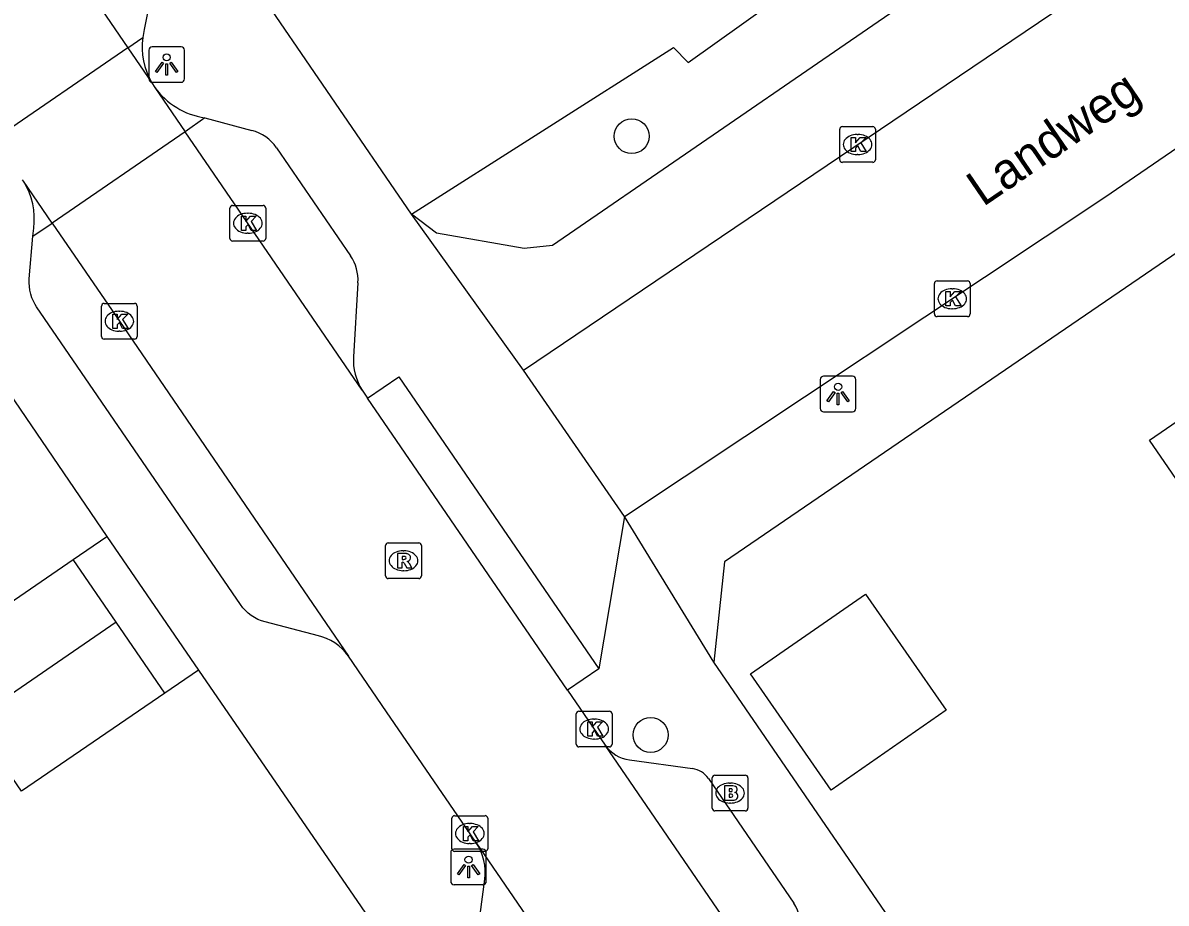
# Model space of a CAD drawing. Extents: x 157466 to 158888, y 383063 to 384677.
# Drawn here: x 158452.4 to 158484.41, y 383630.52 to 383655.18 of the extents above; entities that cross this region are included whole.
import ezdxf

# ---------------------------------------------------------------- set-up
doc = ezdxf.new("R2010")
doc.units = 0
for name, color, linetype in [('IMGEO_Boom', 7, 'Continuous'), ('IMGEO_Brandkraan', 7, 'Continuous'), ('IMGEO_Groenvoorziening', 7, 'Continuous'), ('IMGEO_Kolk', 7, 'Continuous'), ('IMGEO_Lichtpunt', 7, 'Continuous'), ('IMGEO_Openbare_ruimte_label', 7, 'Continuous'), ('IMGEO_Pand', 7, 'Continuous'), ('IMGEO_Parkeervlak_open', 7, 'Continuous'), ('IMGEO_Rijbaan_lokaal_open', 7, 'Continuous'), ('IMGEO_Rioolput', 7, 'Continuous'), ('IMGEO_Voetpad_open', 7, 'Continuous')]:
    doc.layers.add(name, color=color, linetype=linetype)

msp = doc.modelspace()

# ---------------------------------------------------------------- linework, layer by layer
at = {"layer": 'IMGEO_Boom'}
for centre in [(158469.446, 383652.007), (158469.975, 383635.235)]:
    msp.add_circle(centre, 0.489, dxfattribs=at)
at = {"layer": 'IMGEO_Brandkraan'}
for p, q in [((158471.7, 383633.182), (158471.7, 383634.034)), ((158471.775, 383634.108), (158472.627, 383634.108)), ((158472.701, 383634.034), (158472.701, 383633.182)), ((158472.188, 383633.888), (158472.213, 383633.888)), ((158472.627, 383633.108), (158471.775, 383633.108)), ((158472.211, 383633.328), (158472.186, 383633.328))]:
    msp.add_line(p, q, dxfattribs=at)
for points in [[(158471.7, 383633.182), (158471.7, 383634.034)], [(158471.775, 383634.108), (158472.627, 383634.108)], [(158472.701, 383634.034), (158472.701, 383633.182)], [(158472.048, 383633.808), (158472.048, 383633.408), (158472.261, 383633.408)], [(158472.279, 383633.808), (158472.048, 383633.808)], [(158472.227, 383633.727), (158472.173, 383633.727), (158472.173, 383633.651)], [(158472.173, 383633.651), (158472.226, 383633.651)], [(158472.235, 383633.575), (158472.173, 383633.575), (158472.173, 383633.494)], [(158472.173, 383633.494), (158472.235, 383633.494)], [(158472.627, 383633.108), (158471.775, 383633.108)]]:
    msp.add_lwpolyline(points, dxfattribs=at)
for centre, radius, start, end in [((158471.777, 383634.032), 0.0765, 91.552, 178.448), ((158471.777, 383634.032), 0.0765, 91.552, 178.448), ((158472.625, 383634.032), 0.0765, 1.552, 88.448), ((158472.625, 383634.032), 0.0765, 1.552, 88.448), ((158472.228, 383633.689), 0.0379, 267.8285, 90.9355), ((158472.283, 383633.663), 0.145, 59.4692, 91.5367), ((158472.308, 383633.71), 0.0922, 285.5137, 58.1501), ((158472.236, 383633.534), 0.0404, 269.8759, 90.5077), ((158472.267, 383633.659), 0.251, 268.6676, 293.5347), ((158472.313, 383633.518), 0.105, 301.3115, 78.989), ((158471.777, 383633.184), 0.0765, 181.552, 268.448), ((158471.777, 383633.184), 0.0765, 181.552, 268.448), ((158472.625, 383633.184), 0.0765, 271.552, 358.448), ((158472.625, 383633.184), 0.0765, 271.552, 358.448)]:
    msp.add_arc(centre, radius, start, end, dxfattribs=at)
for centre, major_axis, ratio, start_param, end_param in [((158472.187, 383633.608), (-0.387, 0.002), 0.722429, 4.712389, 7.853982), ((158472.212, 383633.608), (-0.39, 0.002), 0.717154, 1.570796, 4.712389)]:
    msp.add_ellipse(centre, major_axis=major_axis, ratio=ratio, start_param=start_param, end_param=end_param, dxfattribs=at)
at = {"layer": 'IMGEO_Groenvoorziening'}
msp.add_lwpolyline([(158463.285, 383649.821), (158470.621, 383654.492), (158471.026, 383654.075), (158477.748, 383658.874), (158478.003, 383659.037)], dxfattribs=at)
at = {"layer": 'IMGEO_Kolk'}
for p, q in [((158475.345, 383652.275), (158476.197, 383652.275)), ((158475.27, 383651.349), (158475.27, 383652.201)), ((158475.758, 383652.055), (158475.783, 383652.055)), ((158476.271, 383652.201), (158476.271, 383651.349)), ((158475.781, 383651.495), (158475.756, 383651.495)), ((158476.197, 383651.275), (158475.345, 383651.275)), ((158458.273, 383650.069), (158459.125, 383650.069)), ((158458.198, 383649.143), (158458.198, 383649.995)), ((158458.686, 383649.849), (158458.711, 383649.849)), ((158459.199, 383649.995), (158459.199, 383649.143)), ((158459.125, 383649.069), (158458.273, 383649.069)), ((158458.709, 383649.289), (158458.684, 383649.289)), ((158477.922, 383647.028), (158477.922, 383647.88)), ((158477.997, 383647.954), (158478.849, 383647.954)), ((158478.923, 383647.88), (158478.923, 383647.028)), ((158478.41, 383647.734), (158478.435, 383647.734)), ((158454.6, 383646.397), (158454.6, 383647.249)), ((158454.675, 383647.323), (158455.527, 383647.323)), ((158455.601, 383647.249), (158455.601, 383646.397)), ((158478.433, 383647.174), (158478.408, 383647.174)), ((158455.088, 383647.103), (158455.113, 383647.103)), ((158478.849, 383646.954), (158477.997, 383646.954)), ((158455.111, 383646.543), (158455.086, 383646.543)), ((158455.527, 383646.323), (158454.675, 383646.323)), ((158467.895, 383634.975), (158467.895, 383635.827)), ((158467.97, 383635.901), (158468.822, 383635.901)), ((158468.383, 383635.681), (158468.408, 383635.681)), ((158468.896, 383635.827), (158468.896, 383634.975)), ((158468.406, 383635.121), (158468.381, 383635.121)), ((158468.822, 383634.901), (158467.97, 383634.901)), ((158464.414, 383632.048), (158464.414, 383632.9)), ((158464.489, 383632.974), (158465.341, 383632.974)), ((158464.902, 383632.754), (158464.927, 383632.754)), ((158465.415, 383632.9), (158465.415, 383632.048)), ((158464.925, 383632.194), (158464.9, 383632.194)), ((158465.341, 383631.974), (158464.489, 383631.974))]:
    msp.add_line(p, q, dxfattribs=at)
for points in [[(158475.345, 383652.275), (158476.197, 383652.275)], [(158475.27, 383651.349), (158475.27, 383652.201)], [(158475.591, 383651.975), (158475.714, 383651.975), (158475.714, 383651.824), (158475.844, 383651.975), (158476.008, 383651.975), (158475.862, 383651.824), (158476.015, 383651.575), (158475.863, 383651.575), (158475.778, 383651.739), (158475.714, 383651.672), (158475.714, 383651.575), (158475.591, 383651.575), (158475.591, 383651.975)], [(158476.271, 383652.201), (158476.271, 383651.349)], [(158476.197, 383651.275), (158475.345, 383651.275)], [(158458.273, 383650.069), (158459.125, 383650.069)], [(158458.198, 383649.143), (158458.198, 383649.995)], [(158458.519, 383649.769), (158458.642, 383649.769), (158458.642, 383649.618), (158458.772, 383649.769), (158458.936, 383649.769), (158458.79, 383649.618), (158458.943, 383649.369), (158458.791, 383649.369), (158458.706, 383649.533), (158458.642, 383649.466), (158458.642, 383649.369), (158458.519, 383649.369), (158458.519, 383649.769)], [(158459.199, 383649.995), (158459.199, 383649.143)], [(158459.125, 383649.069), (158458.273, 383649.069)], [(158477.922, 383647.028), (158477.922, 383647.88)], [(158477.997, 383647.954), (158478.849, 383647.954)], [(158478.923, 383647.88), (158478.923, 383647.028)], [(158478.243, 383647.654), (158478.366, 383647.654), (158478.366, 383647.503), (158478.496, 383647.654), (158478.66, 383647.654), (158478.514, 383647.503), (158478.667, 383647.254), (158478.515, 383647.254), (158478.43, 383647.418), (158478.366, 383647.351), (158478.366, 383647.254), (158478.243, 383647.254), (158478.243, 383647.654)], [(158454.6, 383646.397), (158454.6, 383647.249)], [(158454.675, 383647.323), (158455.527, 383647.323)], [(158455.601, 383647.249), (158455.601, 383646.397)], [(158454.921, 383647.023), (158455.044, 383647.023), (158455.044, 383646.872), (158455.174, 383647.023), (158455.338, 383647.023), (158455.192, 383646.872), (158455.345, 383646.623), (158455.193, 383646.623), (158455.108, 383646.787), (158455.044, 383646.72), (158455.044, 383646.623), (158454.921, 383646.623), (158454.921, 383647.023)], [(158478.849, 383646.954), (158477.997, 383646.954)], [(158455.527, 383646.323), (158454.675, 383646.323)], [(158467.895, 383634.975), (158467.895, 383635.827)], [(158467.97, 383635.901), (158468.822, 383635.901)], [(158468.216, 383635.601), (158468.339, 383635.601), (158468.339, 383635.45), (158468.469, 383635.601), (158468.633, 383635.601), (158468.487, 383635.45), (158468.64, 383635.201), (158468.488, 383635.201), (158468.403, 383635.365), (158468.339, 383635.298), (158468.339, 383635.201), (158468.216, 383635.201), (158468.216, 383635.601)], [(158468.896, 383635.827), (158468.896, 383634.975)], [(158468.822, 383634.901), (158467.97, 383634.901)], [(158464.414, 383632.048), (158464.414, 383632.9)], [(158464.489, 383632.974), (158465.341, 383632.974)], [(158465.415, 383632.9), (158465.415, 383632.048)], [(158464.735, 383632.674), (158464.858, 383632.674), (158464.858, 383632.523), (158464.988, 383632.674), (158465.152, 383632.674), (158465.006, 383632.523), (158465.159, 383632.274), (158465.007, 383632.274), (158464.922, 383632.438), (158464.858, 383632.371), (158464.858, 383632.274), (158464.735, 383632.274), (158464.735, 383632.674)], [(158465.341, 383631.974), (158464.489, 383631.974)]]:
    msp.add_lwpolyline(points, dxfattribs=at)
for centre, start, end in [((158475.347, 383652.199), 91.552, 178.448), ((158475.347, 383652.199), 91.552, 178.448), ((158476.195, 383652.199), 1.552, 88.448), ((158476.195, 383652.199), 1.552, 88.448), ((158475.347, 383651.351), 181.552, 268.448), ((158475.347, 383651.351), 181.552, 268.448), ((158476.195, 383651.351), 271.552, 358.448), ((158476.195, 383651.351), 271.552, 358.448), ((158458.275, 383649.993), 91.552, 178.448), ((158458.275, 383649.993), 91.552, 178.448), ((158459.123, 383649.993), 1.552, 88.448), ((158459.123, 383649.993), 1.552, 88.448), ((158458.275, 383649.145), 181.552, 268.448), ((158458.275, 383649.145), 181.552, 268.448), ((158459.123, 383649.145), 271.552, 358.448), ((158459.123, 383649.145), 271.552, 358.448), ((158477.999, 383647.878), 91.552, 178.448), ((158477.999, 383647.878), 91.552, 178.448), ((158478.847, 383647.878), 1.552, 88.448), ((158478.847, 383647.878), 1.552, 88.448), ((158454.677, 383647.247), 91.552, 178.448), ((158454.677, 383647.247), 91.552, 178.448), ((158455.525, 383647.247), 1.552, 88.448), ((158455.525, 383647.247), 1.552, 88.448), ((158477.999, 383647.03), 181.552, 268.448), ((158477.999, 383647.03), 181.552, 268.448), ((158478.847, 383647.03), 271.552, 358.448), ((158478.847, 383647.03), 271.552, 358.448), ((158454.677, 383646.399), 181.552, 268.448), ((158454.677, 383646.399), 181.552, 268.448), ((158455.525, 383646.399), 271.552, 358.448), ((158455.525, 383646.399), 271.552, 358.448), ((158467.972, 383635.825), 91.552, 178.448), ((158467.972, 383635.825), 91.552, 178.448), ((158468.82, 383635.825), 1.552, 88.448), ((158468.82, 383635.825), 1.552, 88.448), ((158467.972, 383634.977), 181.552, 268.448), ((158467.972, 383634.977), 181.552, 268.448), ((158468.82, 383634.977), 271.552, 358.448), ((158468.82, 383634.977), 271.552, 358.448), ((158464.491, 383632.898), 91.552, 178.448), ((158464.491, 383632.898), 91.552, 178.448), ((158465.339, 383632.898), 1.552, 88.448), ((158465.339, 383632.898), 1.552, 88.448), ((158464.491, 383632.05), 181.552, 268.448), ((158464.491, 383632.05), 181.552, 268.448), ((158465.339, 383632.05), 271.552, 358.448), ((158465.339, 383632.05), 271.552, 358.448)]:
    msp.add_arc(centre, 0.0765, start, end, dxfattribs=at)
for centre, major_axis, ratio, start_param, end_param in [((158475.757, 383651.775), (-0.387, 0.002), 0.722429, 4.712389, 7.853982), ((158475.782, 383651.775), (-0.39, 0.002), 0.717154, 1.570796, 4.712389), ((158458.685, 383649.569), (-0.387, 0.002), 0.722429, 4.712389, 7.853982), ((158458.71, 383649.569), (-0.39, 0.002), 0.717154, 1.570796, 4.712389), ((158478.409, 383647.454), (-0.387, 0.002), 0.722429, 4.712389, 7.853982), ((158478.434, 383647.454), (-0.39, 0.002), 0.717154, 1.570796, 4.712389), ((158455.087, 383646.823), (-0.387, 0.002), 0.722429, 4.712389, 7.853982), ((158455.112, 383646.823), (-0.39, 0.002), 0.717154, 1.570796, 4.712389), ((158468.382, 383635.401), (-0.387, 0.002), 0.722429, 4.712389, 7.853982), ((158468.407, 383635.401), (-0.39, 0.002), 0.717154, 1.570796, 4.712389), ((158464.901, 383632.474), (-0.387, 0.002), 0.722429, 4.712389, 7.853982), ((158464.926, 383632.474), (-0.39, 0.002), 0.717154, 1.570796, 4.712389)]:
    msp.add_ellipse(centre, major_axis=major_axis, ratio=ratio, start_param=start_param, end_param=end_param, dxfattribs=at)
at = {"layer": 'IMGEO_Lichtpunt'}
for p, q in [((158456.83, 383654.513), (158456.022, 383654.513)), ((158456.83, 383654.513), (158456.022, 383654.513)), ((158455.928, 383654.418), (158455.928, 383653.611)), ((158455.928, 383654.418), (158455.928, 383653.611)), ((158456.924, 383653.611), (158456.924, 383654.418)), ((158456.924, 383653.611), (158456.924, 383654.418)), ((158456.022, 383653.517), (158456.83, 383653.517)), ((158456.022, 383653.517), (158456.83, 383653.517)), ((158475.629, 383645.284), (158474.821, 383645.284)), ((158475.629, 383645.284), (158474.821, 383645.284)), ((158474.727, 383645.189), (158474.727, 383644.382)), ((158474.727, 383645.189), (158474.727, 383644.382)), ((158475.723, 383644.382), (158475.723, 383645.189)), ((158475.723, 383644.382), (158475.723, 383645.189)), ((158474.821, 383644.288), (158475.629, 383644.288)), ((158474.821, 383644.288), (158475.629, 383644.288)), ((158464.379, 383631.943), (158464.379, 383631.136)), ((158464.379, 383631.943), (158464.379, 383631.136)), ((158465.281, 383632.038), (158464.473, 383632.038)), ((158465.281, 383632.038), (158464.473, 383632.038)), ((158465.375, 383631.136), (158465.375, 383631.943)), ((158465.375, 383631.136), (158465.375, 383631.943)), ((158464.473, 383631.042), (158465.281, 383631.042)), ((158464.473, 383631.042), (158465.281, 383631.042))]:
    msp.add_line(p, q, dxfattribs=at)
for points in [[(158456.302, 383654.082), (158456.341, 383654.054), (158456.153, 383653.792), (158456.115, 383653.819), (158456.302, 383654.082)], [(158456.404, 383654.034), (158456.451, 383654.034), (158456.451, 383653.712), (158456.404, 383653.712), (158456.404, 383654.034)], [(158456.514, 383654.054), (158456.552, 383654.081), (158456.739, 383653.819), (158456.7, 383653.791), (158456.514, 383654.054)], [(158475.101, 383644.853), (158475.14, 383644.825), (158474.952, 383644.563), (158474.914, 383644.59), (158475.101, 383644.853)], [(158475.203, 383644.805), (158475.25, 383644.805), (158475.25, 383644.483), (158475.203, 383644.483), (158475.203, 383644.805)], [(158475.313, 383644.825), (158475.351, 383644.852), (158475.538, 383644.59), (158475.499, 383644.562), (158475.313, 383644.825)], [(158464.753, 383631.607), (158464.792, 383631.579), (158464.604, 383631.317), (158464.566, 383631.344), (158464.753, 383631.607)], [(158464.855, 383631.559), (158464.902, 383631.559), (158464.902, 383631.237), (158464.855, 383631.237), (158464.855, 383631.559)], [(158464.965, 383631.579), (158465.003, 383631.606), (158465.19, 383631.344), (158465.151, 383631.316), (158464.965, 383631.579)]]:
    msp.add_lwpolyline(points, dxfattribs=at)
for centre in [(158456.427, 383654.216), (158475.226, 383644.987), (158464.878, 383631.741)]:
    msp.add_circle(centre, 0.0994, dxfattribs=at)
for centre, start, end in [((158456.022, 383654.418), 90, 180), ((158456.022, 383654.418), 90, 180), ((158456.83, 383654.418), 0, 90), ((158456.83, 383654.418), 0, 90), ((158456.022, 383653.611), 180, 270), ((158456.022, 383653.611), 180, 270), ((158456.83, 383653.611), 270, 0), ((158456.83, 383653.611), 270, 360), ((158474.821, 383645.189), 90, 180), ((158474.821, 383645.189), 90, 180), ((158475.629, 383645.189), 0, 90), ((158475.629, 383645.189), 0, 90), ((158474.821, 383644.382), 180, 270), ((158474.821, 383644.382), 180, 270), ((158475.629, 383644.382), 270, 0), ((158475.629, 383644.382), 270, 360), ((158464.473, 383631.943), 90, 180), ((158464.473, 383631.943), 90, 180), ((158465.281, 383631.943), 0, 90), ((158465.281, 383631.943), 0, 90), ((158464.473, 383631.136), 180, 270), ((158464.473, 383631.136), 180, 270), ((158465.281, 383631.136), 270, 0), ((158465.281, 383631.136), 270, 360)]:
    msp.add_arc(centre, 0.0946, start, end, dxfattribs=at)
at = {"layer": 'IMGEO_Pand'}
for points in [[(158491.269, 383638.947), (158491.142, 383639.132), (158488.285, 383637.172), (158483.945, 383643.495), (158486.802, 383645.456), (158486.585, 383645.772), (158492.644, 383649.923), (158497.332, 383643.087)], [(158450.998, 383635.64), (158449.792, 383637.399), (158453.804, 383640.15)], [(158455.011, 383638.39), (158453.804, 383640.15)], [(158475.035, 383633.693), (158472.775, 383636.945), (158475.99, 383639.179), (158478.25, 383635.928), (158475.035, 383633.693)], [(158455.011, 383638.39), (158450.998, 383635.64)], [(158456.37, 383636.408), (158455.011, 383638.39)], [(158456.37, 383636.408), (158452.358, 383633.656), (158450.998, 383635.64)]]:
    msp.add_lwpolyline(points, dxfattribs=at)
at = {"layer": 'IMGEO_Parkeervlak_open'}
for points in [[(158455.335, 383654.483), (158455.755, 383654.771)], [(158457.492, 383652.523), (158456.945, 383652.13)], [(158452.683, 383649.206), (158453.218, 383649.573)]]:
    msp.add_lwpolyline(points, dxfattribs=at)
at = {"layer": 'IMGEO_Rijbaan_lokaal_open'}
for points in [[(158466.416, 383645.45), (158489.713, 383661.198), (158492.737, 383663.242), (158495.864, 383665.356), (158498.91, 383667.415), (158500, 383668.152), (158504.557, 383671.274), (158517.062, 383679.907), (158520.659, 383682.363)], [(158469.244, 383641.352), (158482.695, 383650.296), (158498.727, 383661.295), (158500, 383662.168), (158501.86, 383663.444), (158510.016, 383669.039), (158512.882, 383671), (158522.61, 383677.706), (158529.482, 383682.419)], [(158436.987, 383681.311), (158455.335, 383654.483)], [(158455.335, 383654.483), (158451.608, 383651.926)], [(158455.335, 383654.483), (158456.012, 383653.501)], [(158456.012, 383653.501), (158456.092, 383653.375)], [(158456.092, 383653.375), (158456.945, 383652.13)], [(158456.945, 383652.13), (158453.218, 383649.573)], [(158461.899, 383644.892), (158456.945, 383652.13)], [(158452.414, 383650.746), (158452.385, 383650.789)], [(158453.218, 383649.573), (158452.414, 383650.746)], [(158453.218, 383649.573), (158455.102, 383646.823), (158461.52, 383637.441)], [(158469.244, 383641.352), (158466.416, 383645.45)], [(158461.899, 383644.892), (158462.049, 383644.672)], [(158467.65, 383636.489), (158462.049, 383644.672)], [(158465.095, 383632.213), (158465.083, 383632.231), (158464.804, 383632.639), (158462.585, 383635.883), (158461.52, 383637.441)], [(158467.65, 383636.489), (158468.703, 383634.95)], [(158474.159, 383626.979), (158468.703, 383634.95)], [(158465.095, 383632.213), (158474, 383619.196), (158482.506, 383606.965), (158483.545, 383605.497), (158485.16, 383603.044)]]:
    msp.add_lwpolyline(points, dxfattribs=at)
at = {"layer": 'IMGEO_Rioolput'}
for p, q in [((158462.556, 383639.69), (158462.556, 383640.542)), ((158462.631, 383640.616), (158463.483, 383640.616)), ((158463.557, 383640.542), (158463.557, 383639.69)), ((158463.044, 383640.396), (158463.069, 383640.396)), ((158463.067, 383639.836), (158463.042, 383639.836)), ((158463.483, 383639.616), (158462.631, 383639.616))]:
    msp.add_line(p, q, dxfattribs=at)
for points in [[(158462.556, 383639.69), (158462.556, 383640.542)], [(158462.631, 383640.616), (158463.483, 383640.616)], [(158463.557, 383640.542), (158463.557, 383639.69)], [(158463.145, 383640.314), (158462.893, 383640.316), (158462.893, 383639.916)], [(158463.071, 383640.235), (158463.017, 383640.235), (158463.017, 383640.154)], [(158463.017, 383640.154), (158463.069, 383640.154)], [(158462.893, 383639.916), (158463.017, 383639.916), (158463.017, 383640.078), (158463.028, 383640.078)], [(158463.075, 383640.049), (158463.146, 383639.916), (158463.286, 383639.916), (158463.221, 383640.042)], [(158463.483, 383639.616), (158462.631, 383639.616)]]:
    msp.add_lwpolyline(points, dxfattribs=at)
for centre, radius, start, end in [((158462.633, 383640.54), 0.0765, 91.552, 178.448), ((158462.633, 383640.54), 0.0765, 91.552, 178.448), ((158463.481, 383640.54), 0.0765, 1.552, 88.448), ((158463.481, 383640.54), 0.0765, 1.552, 88.448), ((158463.053, 383640.343), 0.19, 274.7715, 282.9687), ((158463.077, 383640.139), 0.0964, 77.0061, 93.1865), ((158463.091, 383640.196), 0.0378, 276.6634, 79.6772), ((158463.144, 383640.204), 0.109, 350.3612, 89.416), ((158463.142, 383640.204), 0.112, 277.5842, 350.9817), ((158463.126, 383639.989), 0.108, 29.5134, 73.7905), ((158463.027, 383640.025), 0.0533, 26.0293, 88.6989), ((158462.633, 383639.692), 0.0765, 181.552, 268.448), ((158462.633, 383639.692), 0.0765, 181.552, 268.448), ((158463.481, 383639.692), 0.0765, 271.552, 358.448), ((158463.481, 383639.692), 0.0765, 271.552, 358.448)]:
    msp.add_arc(centre, radius, start, end, dxfattribs=at)
for centre, major_axis, ratio, start_param, end_param in [((158463.043, 383640.116), (-0.387, 0.002), 0.722429, 4.712389, 7.853982), ((158463.068, 383640.116), (-0.39, 0.002), 0.717154, 1.570796, 4.712389)]:
    msp.add_ellipse(centre, major_axis=major_axis, ratio=ratio, start_param=start_param, end_param=end_param, dxfattribs=at)
at = {"layer": 'IMGEO_Voetpad_open'}
for points in [[(158463.285, 383649.821), (158413.081, 383723.175)], [(158479.294, 383657.245), (158467.233, 383648.945), (158466.434, 383648.858), (158463.98, 383649.287), (158463.285, 383649.821)], [(158456.02, 383656.138), (158455.797, 383654.993), (158455.755, 383654.771)], [(158493.557, 383654.787), (158472.047, 383640.083), (158471.744, 383637.271)], [(158457.492, 383652.523), (158458.815, 383652.168)], [(158459.5, 383651.685), (158461.575, 383648.655)], [(158452.683, 383649.206), (158452.702, 383649.432), (158452.719, 383649.603), (158452.72, 383649.775), (158452.706, 383649.946), (158452.677, 383650.115), (158452.632, 383650.281), (158452.574, 383650.442), (158452.5, 383650.598), (158452.414, 383650.746)], [(158466.416, 383645.45), (158463.285, 383649.821)], [(158461.52, 383637.441), (158461.436, 383637.546), (158461.344, 383637.644), (158461.243, 383637.733), (158461.134, 383637.812), (158461.019, 383637.881), (158460.898, 383637.94), (158460.772, 383637.988), (158460.677, 383638.016), (158459.183, 383638.401), (158459.082, 383638.432), (158458.982, 383638.473), (158458.886, 383638.523), (158458.795, 383638.581), (158458.709, 383638.646), (158458.63, 383638.72), (158458.557, 383638.8), (158458.492, 383638.886), (158452.785, 383647.23), (158452.746, 383647.291), (158452.695, 383647.385), (158452.653, 383647.483), (158452.62, 383647.585), (158452.595, 383647.69), (158452.581, 383647.796), (158452.576, 383647.903), (158452.58, 383648.01), (158452.683, 383649.206)], [(158461.782, 383647.902), (158461.653, 383645.83)], [(158451.556, 383645.471), (158454.748, 383640.795)], [(158462.049, 383644.672), (158462.924, 383645.271), (158468.525, 383637.088)], [(158469.244, 383641.352), (158468.525, 383637.088)], [(158471.744, 383637.271), (158469.244, 383641.352)], [(158453.804, 383640.15), (158454.748, 383640.795)], [(158454.748, 383640.795), (158457.32, 383637.049)], [(158493.546, 383607.43), (158491.931, 383607.828), (158471.744, 383637.271)], [(158457.32, 383637.049), (158456.37, 383636.408)], [(158457.32, 383637.049), (158480.295, 383603.601), (158481.671, 383601.572)], [(158468.525, 383637.088), (158467.65, 383636.489)], [(158469.382, 383634.538), (158471.146, 383634.293)], [(158471.593, 383634.016), (158473.983, 383630.524)], [(158465.139, 383629.708), (158465.333, 383631.191), (158465.344, 383631.324), (158465.344, 383631.458), (158465.331, 383631.592), (158465.306, 383631.723), (158465.27, 383631.852), (158465.223, 383631.978), (158465.164, 383632.098), (158465.095, 383632.213)]]:
    msp.add_lwpolyline(points, dxfattribs=at)
for centre, radius, start, end in [((158457.743, 383654.512), 2.005, 172.5858, 210.2942), ((158457.806, 383654.615), 2.115, 215.8859, 261.4671), ((158458.507, 383651.005), 1.203, 34.4319, 75.192), ((158460.577, 383647.976), 1.207, 356.4962, 34.2457), ((158463.293, 383645.759), 1.641, 177.515, 211.8759), ((158469.521, 383635.532), 1.004, 215.4474, 262.056), ((158471.059, 383633.653), 0.646, 34.2029, 82.2252), ((158473.038, 383629.875), 1.146, 349.5264, 34.453)]:
    msp.add_arc(centre, radius, start, end, dxfattribs=at)

# ---------------------------------------------------------------- texts
at = {"layer": 'IMGEO_Openbare_ruimte_label'}
msp.add_text('Landweg', height=1, rotation=34.3256, dxfattribs=at).set_placement((158479.282, 383650.014))

doc.saveas('drawing.dxf')
